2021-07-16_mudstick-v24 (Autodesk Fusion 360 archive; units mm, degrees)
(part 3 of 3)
sketch "Sketch60" plane through (0, 5, 0) normal (0, 1, 0) x axis (-1, 0, 0)
  line L1 (-35, 115) -> (9, 115)
  line L2 (-35, 0) -> (-35, 115)
  line L3 (35, 0) -> (-35, 0)
  line L4 (35, 119) -> (35, 0)
  line L5 (25.5, 119) -> (35, 119)
  line L6 (25.5, 153) -> (25.5, 119)
  line L7 (35, 153) -> (25.5, 153)
  line L8 (35, 170.5) -> (35, 153)
  line L9 (29, 170.5) -> (35, 170.5)
  line L10 (29, 160.25) -> (29, 170.5)
  line L11 (15, 160.25) -> (29, 160.25)
  line L12 (15, 170.5) -> (15, 160.25)
  line L13 (9, 170.5) -> (15, 170.5)
  line L14 (9, 115) -> (9, 170.5)
  line L15 (-22, 10) -> (22, 10)
  line L16 (-22, 100) -> (-22, 10)
  line L17 (22, 100) -> (-22, 100)
  line L18 (22, 10) -> (22, 100)
  line L19 (0, 0) -> (0, 10)
  line L20 (-17.9585, 10) -> (-19.9793, 6.5)
  line L21 (-19.9793, 13.5) -> (-17.9585, 10)
  line L22 (-24.0207, 13.5) -> (-19.9793, 13.5)
  line L23 (-26.0415, 10) -> (-24.0207, 13.5)
  line L24 (-24.0207, 6.5) -> (-26.0415, 10)
  line L25 (-19.9793, 6.5) -> (-24.0207, 6.5)
  line L26 (-26.0415, 100) -> (-24.0207, 103.5)
  line L27 (-19.9793, 103.5) -> (-17.9585, 100)
  line L28 (-24.0207, 96.5) -> (-26.0415, 100)
  line L29 (-24.0207, 103.5) -> (-19.9793, 103.5)
  line L30 (-17.9585, 100) -> (-19.9793, 96.5)
  line L31 (-19.9793, 96.5) -> (-24.0207, 96.5)
  line L32 (17.9585, 10) -> (19.9793, 13.5)
  line L33 (24.0207, 13.5) -> (26.0415, 10)
  line L34 (19.9793, 6.5) -> (17.9585, 10)
  line L35 (19.9793, 13.5) -> (24.0207, 13.5)
  line L36 (26.0415, 10) -> (24.0207, 6.5)
  line L37 (24.0207, 6.5) -> (19.9793, 6.5)
  line L38 (17.9585, 100) -> (19.9793, 103.5)
  line L39 (24.0207, 103.5) -> (26.0415, 100)
  line L40 (19.9793, 96.5) -> (17.9585, 100)
  line L41 (19.9793, 103.5) -> (24.0207, 103.5)
  line L42 (26.0415, 100) -> (24.0207, 96.5)
  line L43 (24.0207, 96.5) -> (19.9793, 96.5)
  line L44 (-22, 157) -> (-22, 100)
  line L45 (-24.0207, 160.5) -> (-19.9793, 160.5)
  line L46 (-17.9585, 157) -> (-19.9793, 153.5)
  line L47 (-19.9793, 160.5) -> (-17.9585, 157)
  line L48 (-26.0415, 157) -> (-24.0207, 160.5)
  line L49 (-19.9793, 153.5) -> (-24.0207, 153.5)
  line L50 (-24.0207, 153.5) -> (-26.0415, 157)
  line L51 (9, 170.5) -> (9, 115)
  line L52 (9, 115) -> (-35, 115)
  line L53 (-35, 170.5) -> (9, 170.5)
  line L54 (-35, 115) -> (-35, 170.5)
  circle C1 centre (14, 115.5) radius 1.7
  circle C2 centre (30, 115.5) radius 1.7
  circle C3 centre (14, 156.5) radius 1.7
  circle C4 centre (30, 156.5) radius 1.7
  circle C5 centre (23, 81) radius 1.65
  circle C6 centre (29, 6) radius 1.65
  circle C7 centre (-29, 33.75) radius 1.65
  circle C8 centre (-22, 10) radius 2.125
  circle C9 centre (-22, 100) radius 2.125
  circle C10 centre (22, 10) radius 2.125
  circle C11 centre (22, 100) radius 2.125
  circle C12 centre (-22, 157) radius 2.125
  point P27 (0, 10)
  point P1 (0, 0)
  point P28 (0, 0)
  point P29 (-22, 10)
  point P36 (-22, 10)
  point P43 (-22, 100)
  point P44 (-22, 100)
  point P51 (22, 10)
  point P52 (22, 10)
  point P59 (22, 100)
  point P60 (22, 100)
  point P24 (-22, 10)
  point P25 (-22, 100)
  point P26 (22, 100)
  point P23 (22, 10)
  point P61 (-22, 100)
  point P67 (-22, 157)
  point P72 (-22, 157)
  point P68 (-22, 157)
  point P63 (-22, 157)
  point P62 (-22, 157)
  point P74 (9, 170.5)
  point P76 (9, 170.5)
  point P5 (-35, 115)
  point P78 (-35, 115)
  point P33 (-24.0207, 13.5)
  point P37 (-24.0207, 103.5)
  point P45 (19.9793, 13.5)
  point P53 (19.9793, 103.5)
  point P65 (-24.0207, 160.5)
  horizontal L15
  vertical L16
  horizontal L17
  vertical L18
  midpoint L15 P27
  coincident P1 P28
  vertical L19
  coincident P29 P36
  horizontal L25
  coincident P43 P44
  horizontal L31
  coincident P51 P52
  horizontal L37
  coincident P59 P60
  horizontal L43
  coincident P24 P29
  coincident P25 P43
  coincident P26 P59
  coincident P23 P52
  coincident P43 P61
  perpendicular L29 L44
  coincident P67 P72
  horizontal L49
  coincident P68 P72
  coincident P63 P72
  coincident P62 P63
  coincident P74 P76
  perpendicular L51 L53
  perpendicular L13 L54
  coincident P5 P78
  dimension "d2277" distance P25 P26 = 44
  dimension "d2278" distance P24 P25 = 90
  dimension "d2279" distance P27 P28 = 10
  dimension "d2280" diameter C8 = 4.25
  dimension "d2281" distance P33 L25 = 7
  dimension "d2282" diameter C9 = 4.25
  dimension "d2283" distance P37 L31 = 7
  dimension "d2284" diameter C10 = 4.25
  dimension "d2285" distance P45 L37 = 7
  dimension "d2286" diameter C11 = 4.25
  dimension "d2287" distance P53 L43 = 7
  dimension "d2295" distance P61 P62 = 57
  dimension "d2296" diameter C12 = 4.25
  dimension "d2297" distance P65 L49 = 7
extrude "Extrude218" add sketch "Sketch60" profile of L1 L14 L45 L46 L47 L48 C12 L49 L50 L51 L52 L53 L54 to an object
extrude "Extrude215" cut sketch "Sketch60" profile of C8 C9 C10 C11 C12 to an object
extrude "Extrude216" cut sketch "Sketch60" profile of C8 L20 L21 L22 L23 L24 L25 L26 C9 L27 L28 L29 L30 L31 L32 C10 L33 L34 L35 L36 L37 L38 C11 L39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 against normal blind 6
chamfer "Chamfer25" distance 1.7
component_insert "Component Insert59"
joint "Assemble56" alignAngle 0 alignOffsetX 0 alignOffsetY 0 alignOffsetZ 0
component_insert "Component Insert60"
joint "Assemble57" alignAngle 0 alignOffsetX 0 alignOffsetY 0 alignOffsetZ 0
component_insert "Component Insert61"
joint "Assemble58" alignAngle 0 alignOffsetX 0 alignOffsetY 0 alignOffsetZ 0
component_insert "Component Insert62"
joint "Assemble59" alignAngle 0 alignOffsetX 0 alignOffsetY 0 alignOffsetZ 0
component_insert "Component Insert63"
joint "Assemble60" alignAngle 0 alignOffsetX 0 alignOffsetY 0 alignOffsetZ 0
component_insert "Component Insert64"
joint "Assemble61" alignAngle 0 alignOffsetX 0 alignOffsetY 0 alignOffsetZ 0
component_insert "Component Insert65"
joint "Assemble62" alignAngle 0 alignOffsetX 0 alignOffsetY 0 alignOffsetZ 0
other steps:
joint_origin "JointOrigin52"
joint_origin "JointOrigin53"
joint_origin "JointOrigin54"
joint_origin "JointOrigin55"
joint_origin "JointOrigin56"
joint_origin "JointOrigin57"
joint_origin "JointOrigin58"
joint_origin "JointOrigin59"

design "PULL OUT DOWEL 6x16 97355A292"
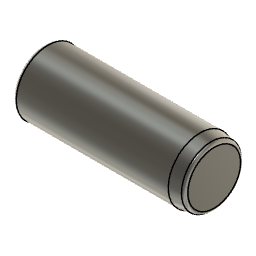
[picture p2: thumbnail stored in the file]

design "BHCS M4 x 25 92095A197"
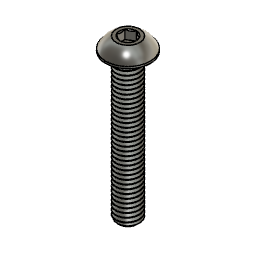
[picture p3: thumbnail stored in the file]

design "BHCS M4x10 92095A190"
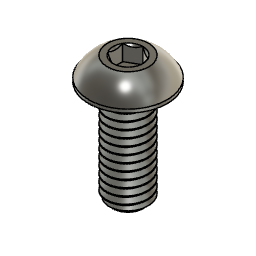
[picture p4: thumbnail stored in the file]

design "Hotplate Pogo Drop"
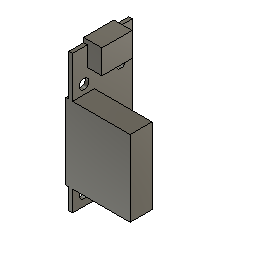
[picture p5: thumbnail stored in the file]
sketch "Sketch1" plane through (0, 0, 0) normal (1, 0, 0) x axis (0, 1, 0)
  line L1 (26, 0) -> (0, 0)
  line L2 (26, 60) -> (26, 0)
  line L3 (0, 60) -> (26, 60)
  line L4 (0, 0) -> (0, 60)
  line L5 (15.5, 49.5) -> (10.5, 49.5)
  line L6 (15.5, 1.5) -> (15.5, 49.5)
  line L7 (10.5, 1.5) -> (15.5, 1.5)
  line L8 (10.5, 49.5) -> (10.5, 1.5)
  line L9 (15.5, 1.5) -> (10.5, 49.5)
  line L10 (13, 0) -> (13, 25.5)
  line L11 (26, 25.5) -> (13, 25.5)
  line L12 (5, 5) -> (5, 46)
  line L13 (21, 5) -> (5, 5)
  line L14 (21, 46) -> (21, 5)
  line L15 (9.5, 42) -> (0, 42)
  line L16 (9.5, 9) -> (9.5, 42)
  line L17 (0, 9) -> (9.5, 9)
  line L18 (21, 46) -> (5, 46)
  line L19 (19.55, 51.5) -> (6.45, 51.5)
  line L20 (19.55, 62) -> (19.55, 51.5)
  line L21 (6.45, 62) -> (19.55, 62)
  line L22 (6.45, 51.5) -> (6.45, 62)
  line L23 (13, 49.5) -> (13, 51.5)
  circle C1 centre (5, 46) radius 2.125
  circle C2 centre (5, 5) radius 2.125
  circle C3 centre (21, 46) radius 2.125
  circle C4 centre (21, 5) radius 2.125
  point P1 (0, 0)
  point P2 (0, 0)
  point P10 (13, 25.5)
  point P11 (13, 0)
  point P13 (5, 46)
  point P17 (5, 46)
  point P14 (5, 5)
  point P18 (5, 5)
  point P19 (5, 5)
  point P16 (21, 5)
  point P20 (21, 5)
  point P21 (21, 5)
  point P15 (21, 46)
  point P22 (21, 46)
  point P23 (0, 42)
  point P26 (0, 9)
  point P27 (9.5, 25.5)
  point P28 (5, 46)
  point P29 (21, 46)
  point P34 (13, 51.5)
  point P35 (13, 49.5)
  point P3 (26, 0)
  point P5 (0, 60)
  point P6 (10.5, 49.5)
  point P9 (10.5, 1.5)
  point P7 (15.5, 49.5)
  point P24 (9.5, 42)
  point P25 (9.5, 9)
  point P32 (19.55, 62)
  point P33 (6.45, 62)
  horizontal L1
  vertical L2
  horizontal L3
  vertical L4
  coincident P1 P2
  horizontal L5
  vertical L6
  horizontal L7
  vertical L8
  midpoint L9 P10
  coincident L1 P11
  perpendicular L1 L10
  horizontal L11
  equal C3 C4
  equal C1 C4
  equal C1 C2
  coincident P13 P17
  vertical L12
  coincident P14 P18
  coincident P14 P19
  coincident P16 P20
  horizontal L13
  coincident P16 P21
  perpendicular L13 L14
  coincident P15 P22
  coincident L4 P23
  perpendicular L4 L15
  perpendicular L15 L16
  coincident L4 P26
  perpendicular L4 L17
  midpoint L16 P27
  coincident L11 P27
  coincident P13 P28
  coincident P15 P29
  horizontal L18
  horizontal L19
  vertical L20
  horizontal L21
  vertical L22
  midpoint L19 P34
  midpoint L5 P35
  vertical L23
  dimension "d1" distance P2 P3 = 26
  dimension "d2" distance P2 P5 = 60
  dimension "d4" distance P1 L10 = 13
  dimension "d5" distance P6 P9 = 48 (= "( 24 * 2 ) * 1 mm")
  dimension "d6" distance P6 P7 = 5
  dimension "d7" diameter C1 = 4.25
  dimension "d9" distance L4 P13 = 5
  dimension "d23" distance P23 P24 = 9.5
  dimension "d24" distance P24 P25 = 33
  dimension "d25" distance L1 P27 = 25.5
  dimension "d26" distance L3 L18 = 14
  dimension "d27" distance L1 P14 = 5
  dimension "d28" distance L10 L14 = 8
  dimension "d29" distance P32 P33 = 13.1
  dimension "d30" distance L3 L21 = 2
  dimension "d31" distance P7 L19 = 2
extrude "Extrude1" new body sketch "Sketch1" profile of L1 L2 L3 L4 L5 L6 L7 L8 C1 C2 C3 C4 along normal blind 1.6
extrude "Extrude2" add sketch "Sketch1" profile of L5 L6 L7 L8 against normal blind 0.5
extrude "Extrude3" sketch "Sketch1" profile of L4 L15 L16 L17 blind 25
extrude "Extrude4" add sketch "Sketch1" profile of L4 L15 L16 L17 against normal blind 1.2448 (magnitude of "-0.112 in + 1.6 mm")
extrude "Extrude5" add sketch "Sketch1" profile of L3 L19 L20 L21 L22 to an object offset 6.3

design "2298K420_METRIC QUICK-GRIP SCREW-CLAMP BUSHING"
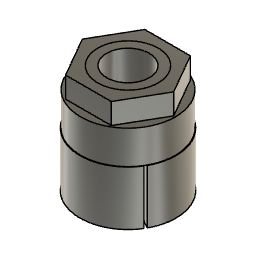
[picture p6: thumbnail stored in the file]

design "N17 48mm"
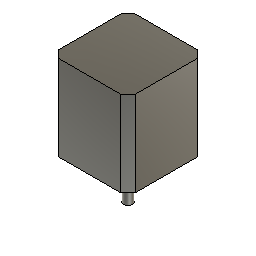
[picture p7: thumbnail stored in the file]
sketch "Sketch1" plane through (0, 0, 0) normal (0, 0, 1) x axis (1, 0, 0)
  line L1 (-21.6, 21.6) -> (21.6, 21.6)
  line L2 (-21.6, -21.6) -> (-21.6, 21.6)
  line L3 (21.6, 21.6) -> (21.6, -21.6)
  line L4 (21.6, 21.6) -> (21.6, 21.6)
  line L5 (-21.6, -21.6) -> (21.6, 21.6)
  line L6 (21.6, -21.6) -> (-21.6, 21.6)
  line L7 (15.5, 15.5) -> (-15.5, 15.5)
  line L8 (15.5, -15.5) -> (15.5, 15.5)
  line L9 (-15.5, -15.5) -> (15.5, -15.5)
  line L10 (-15.5, 15.5) -> (-15.5, -15.5)
  circle C1 centre (0, 0) radius 11
  circle C2 centre (-15.5, 15.5) radius 1.5
  circle C3 centre (-15.5, -15.5) radius 1.5
  circle C4 centre (15.5, -15.5) radius 1.5
  circle C5 centre (15.5, 15.5) radius 1.5
  circle C6 centre (0, 0) radius 2.5
  point P6 (0, 0)
  point P1 (0, 0)
  point P7 (0, 0)
  point P10 (15.5, -15.5)
  point P8 (-15.5, 15.5)
  point P9 (15.5, 15.5)
  point P12 (-15.5, 15.5)
  point P11 (-15.5, -15.5)
  point P13 (-15.5, -15.5)
  point P14 (15.5, -15.5)
  point P15 (15.5, 15.5)
  point P2 (21.6, 21.6)
  point P3 (-21.6, 21.6)
  perpendicular L1 L2
  parallel L1 L3
  parallel L2 L4
  horizontal L1
  coincident L5 P6
  coincident L6 P6
  coincident P1 P6
  equal L1 L2
  coincident P6 P7
  horizontal L7
  vertical L8
  horizontal L9
  vertical L10
  coincident L6 P10
  coincident L6 P8
  coincident L5 P9
  coincident P8 P12
  coincident P11 P13
  coincident P10 P14
  coincident P9 P15
  equal C2 C5
  equal C2 C3
  equal C2 C4
  concentric C1 C6
  dimension "d1" distance P2 P3 = 43.2
  dimension "d2" diameter C1 = 22
  dimension "d3" distance P8 P9 = 31
  dimension "d4" diameter C2 = 3
  dimension "d5" diameter C6 = 5
extrude "Extrude1" new body sketch "Sketch1" profile of L1 L2 L3 L4 C1 C2 C3 C4 C5 C6 along normal blind 48
extrude "Extrude2" cut sketch "Sketch1" profile of C2 C3 C4 C5 along normal blind 5
extrude "Extrude3" add sketch "Sketch1" profile of C1 C6 against normal blind 2
extrude "Extrude4" add sketch "Sketch1" profile of C6 against normal blind 24
chamfer "Chamfer1" distance 4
